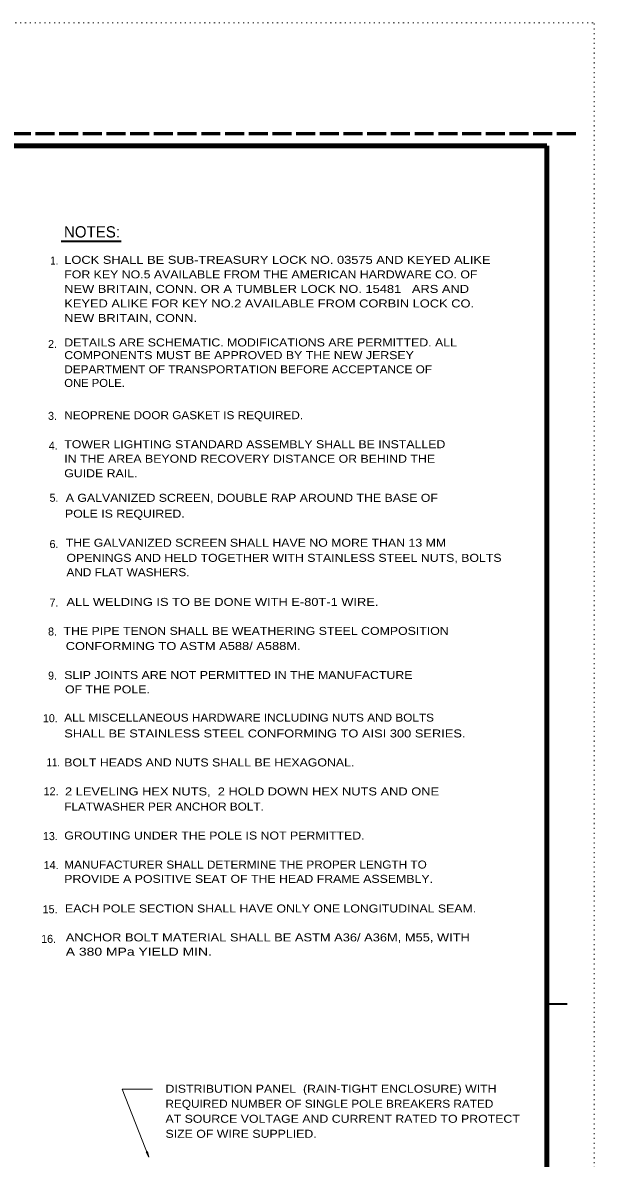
# Model space of a CAD drawing. Extents: x 312583 to 312854, y 144419 to 144597.
# Drawn here: x 312799.2 to 312853.5, y 144489 to 144596.8 of the extents above; entities that cross this region are included whole.
import ezdxf
from ezdxf.enums import TextEntityAlignment as Align

# ---------------------------------------------------------------- set-up
doc = ezdxf.new("R2010")
doc.units = 0
doc.header["$LTSCALE"] = 0.3
doc.linetypes.add('DOTTED', pattern=[1.5, 0.3, -1.2])
doc.linetypes.add('LONG_DASHED', pattern=[7.5, 6, -1.5])
for name, color, linetype, lineweight in [('1', 7, 'Continuous', 13), ('2', 7, 'Continuous', 13), ('61', 7, 'LONG_DASHED', 60), ('63', 7, 'DOTTED', 13)]:
    doc.layers.add(name, color=color, linetype=linetype, lineweight=lineweight)

msp = doc.modelspace()

# ---------------------------------------------------------------- linework, layer by layer
at = {"layer": '1', "lineweight": 158}
msp.add_line((312849, 144423.1446), (312849, 144585.0846), dxfattribs=at)
at = {"layer": '1', "lineweight": 35}
msp.add_line((312849, 144503.6216), (312850.932, 144503.6216), dxfattribs=at)
at = {"layer": '1', "lineweight": 158}
msp.add_lwpolyline([(312616.5, 144423.1446), (312616.5, 144585.0846), (312849, 144585.0846)], dxfattribs=at)
at = {"layer": '1'}
msp.add_lwpolyline([(312811.5575, 144495.5363), (312808.6825, 144495.5363), (312811.2278, 144489.0656)], dxfattribs=at)
msp.add_lwpolyline([(312811.0898, 144489.6023), (312811.2278, 144489.0656), (312810.9518, 144489.5486), (312811.0438, 144489.5256)], close=True, dxfattribs=at)
at = {"layer": '2', "lineweight": 35}
msp.add_line((312802.8959, 144576.0456), (312808.5999, 144576.0456), dxfattribs=at)
at = {"layer": '61'}
msp.add_line((312851.75, 144586.2246), (312583.526, 144586.2246), dxfattribs=at)
at = {"layer": '63'}
msp.add_line((312601.2, 144596.7846), (312853.5, 144596.7846), dxfattribs=at)
msp.add_lwpolyline([(312601.2, 144418.5846), (312853.5, 144418.5846), (312853.5, 144596.7846)], dxfattribs=at)

# ---------------------------------------------------------------- texts
at = {"layer": '1'}
for s, width, p in [('NEOPRENE DOOR GASKET IS REQUIRED.', 1.1, (312803.1873, 144559.1428)), ('MANUFACTURER SHALL DETERMINE THE PROPER LENGTH TO', 1.1, (312803.1872, 144516.4772)), ('PROVIDE A POSITIVE SEAT OF THE HEAD FRAME ASSEMBLY.', 1.15, (312803.1873, 144515.1214)), ('EACH POLE SECTION SHALL HAVE ONLY ONE LONGITUDINAL SEAM.', 1.15, (312803.2573, 144512.3065)), ('ANCHOR BOLT MATERIAL SHALL BE ASTM A36/ A36M, M55, WITH', 1.2, (312803.3274, 144509.5618)), ('A 380 MPa YIELD MIN.', 1.3, (312803.3273, 144508.206)), ('DISTRIBUTION PANEL  (RAIN-TIGHT ENCLOSURE) WITH', 1.15, (312812.7961, 144495.1935)), ('REQUIRED NUMBER OF SINGLE POLE BREAKERS RATED', 1.1, (312812.7961, 144493.7675)), ('AT SOURCE VOLTAGE AND CURRENT RATED TO PROTECT', 1.15, (312812.7961, 144492.3415)), ('SIZE OF WIRE SUPPLIED.', 1.15, (312812.7961, 144490.9155))]:
    msp.add_text(s, height=0.76, dxfattribs=dict(at, width=width)).set_placement(p)
for s, p in [('15.', (312801.1355, 144512.2363)), ('16.', (312800.9954, 144509.4215))]:
    msp.add_text(s, height=0.76, dxfattribs=at).set_placement(p)
at = {"layer": '2'}
msp.add_text('NOTES:', height=1.07, dxfattribs=at).set_placement((312805.82, 144576.3926), align=Align.CENTER)
for s, width, p in [('1.', 0.9, (312801.8591, 144573.8202)), ('LOCK SHALL BE SUB-TREASURY LOCK NO. 03575 AND KEYED ALIKE  ', 1.2, (312803.1873, 144573.8903)), ('FOR KEY NO.5 AVAILABLE FROM THE AMERICAN HARDWARE CO. OF ', 1.15, (312803.1873, 144572.5103)), ('NEW BRITAIN, CONN. OR A TUMBLER LOCK NO. 15481   ARS AND  ', 1.2, (312803.1873, 144571.1303)), ('KEYED ALIKE FOR KEY NO.2 AVAILABLE FROM CORBIN LOCK CO. ', 1.2, (312803.1873, 144569.7503)), ('NEW BRITAIN, CONN. ', 1.2, (312803.1873, 144568.3703)), ('DETAILS ARE SCHEMATIC. MODIFICATIONS ARE PERMITTED. ALL ', 1.15, (312803.1873, 144566.0483)), ('COMPONENTS MUST BE APPROVED BY THE NEW JERSEY ', 1.15, (312803.1873, 144564.8433)), ('DEPARTMENT OF TRANSPORTATION BEFORE ACCEPTANCE OF', 1.1, (312803.1873, 144563.4979)), ('ONE POLE.', 1.05, (312803.1873, 144562.2045)), ('TOWER LIGHTING STANDARD ASSEMBLY SHALL BE INSTALLED', 1.15, (312803.1873, 144556.3866)), ('IN THE AREA BEYOND RECOVERY DISTANCE OR BEHIND THE', 1.15, (312803.1873, 144555.0066)), ('GUIDE RAIL.', 1.15, (312803.1873, 144553.6266)), ('A GALVANIZED SCREEN, DOUBLE RAP AROUND THE BASE OF', 1.15, (312803.3274, 144551.2953)), ('POLE IS REQUIRED.', 1.15, (312803.2573, 144549.7914)), ('THE GALVANIZED SCREEN SHALL HAVE NO MORE THAN 13 MM', 1.15, (312803.3273, 144547.0314)), ('OPENINGS AND HELD TOGETHER WITH STAINLESS STEEL NUTS, BOLTS', 1.15, (312803.3975, 144545.5979)), ('AND FLAT WASHERS.', 1.1, (312803.3974, 144544.2343)), ('ALL WELDING IS TO BE DONE WITH E-80T-1 WIRE.', 1.2, (312803.3974, 144541.4118)), ('THE PIPE TENON SHALL BE WEATHERING STEEL COMPOSITION', 1.15, (312803.1172, 144538.6595)), ('CONFORMING TO ASTM A588/ A588M.', 1.2, (312803.3273, 144537.2258)), ('SLIP JOINTS ARE NOT PERMITTED IN THE MANUFACTURE', 1.15, (312803.1872, 144534.4734)), ('OF THE POLE.', 1.15, (312803.2573, 144533.11)), ('ALL MISCELLANEOUS HARDWARE INCLUDING NUTS AND BOLTS', 1.1, (312803.1872, 144530.4277)), ('SHALL BE STAINLESS STEEL CONFORMING TO AISI 300 SERIES.', 1.2, (312803.1872, 144528.924)), ('11.', 0.9, (312801.5089, 144526.1869)), ('BOLT HEADS AND NUTS SHALL BE HEXAGONAL.', 1.15, (312803.1872, 144526.1716)), ('2 LEVELING HEX NUTS,  2 HOLD DOWN HEX NUTS AND ONE', 1.2, (312803.2573, 144523.4193)), ('FLATWASHER PER ANCHOR BOLT.', 1.1, (312803.1873, 144521.9856)), ('GROUTING UNDER THE POLE IS NOT PERMITTED.', 1.15, (312803.1872, 144519.2333))]:
    msp.add_text(s, height=0.76, dxfattribs=dict(at, width=width)).set_placement(p)
for s, p in [('2.', (312801.6489, 144565.8987)), ('3.', (312801.6489, 144559.0764)), ('4.', (312801.719, 144556.2463)), ('5.', (312801.7891, 144551.3029)), ('6.', (312801.7892, 144546.9065)), ('7.', (312801.7891, 144541.357)), ('8.', (312801.6489, 144538.6047)), ('9.', (312801.649, 144534.4186)), ('10.', (312801.1585, 144530.3729)), ('12.', (312801.2286, 144523.4346)), ('13.', (312801.1585, 144519.1785)), ('14.', (312801.2285, 144516.4261))]:
    msp.add_text(s, height=0.76, dxfattribs=at).set_placement(p)

doc.saveas('drawing.dxf')
